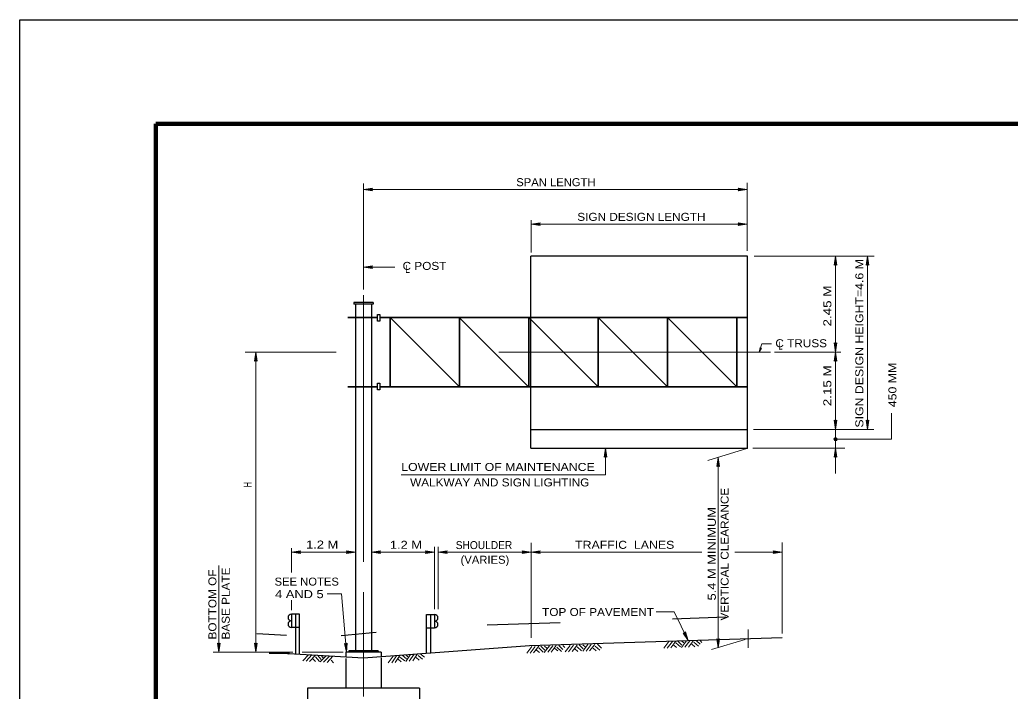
# Model space of a CAD drawing. Extents: x 312601.858 to 312602.699, y 144420.109 to 144420.704.
# Drawn here: x 312601.8578 to 312602.229, y 144420.4517 to 144420.7035 of the extents above; entities that cross this region are included whole.
import ezdxf
from ezdxf.enums import TextEntityAlignment as Align

# ---------------------------------------------------------------- set-up
doc = ezdxf.new("R2010")
doc.units = 0
doc.header["$LTSCALE"] = 0.0012
doc.header["$PDMODE"] = 32
doc.header["$PDSIZE"] = 0.0006
doc.linetypes.add('DOT_DASHED', pattern=[7.7, 5, -1.2, 0.3, -1.2])
doc.linetypes.add('LONG_DASHED', pattern=[7.5, 6, -1.5])
doc.layers.add('1', color=7, linetype='Continuous', lineweight=13)
doc.layers.add('39', color=7, linetype='Continuous', lineweight=13)

msp = doc.modelspace()

# ---------------------------------------------------------------- hatches: boundary and pattern name
at = {"layer": '39'}
for points in [[(312601.9897, 144420.6399), (312601.99, 144420.6394), (312601.9866, 144420.6399), (312601.99, 144420.6404)], [(312602.1274, 144420.6399), (312602.1271, 144420.6404), (312602.1305, 144420.6399), (312602.1271, 144420.6394)], [(312602.0526, 144420.6269), (312602.0529, 144420.6264), (312602.0495, 144420.6269), (312602.0529, 144420.6274)], [(312602.1274, 144420.6269), (312602.1271, 144420.6274), (312602.1305, 144420.6269), (312602.1271, 144420.6264)], [(312602.1636, 144420.6118), (312602.1631, 144420.6115), (312602.1636, 144420.6149), (312602.1641, 144420.6115)], [(312602.1756, 144420.6118), (312602.1751, 144420.6115), (312602.1756, 144420.6149), (312602.1761, 144420.6115)], [(312602.1756, 144420.6118), (312602.1751, 144420.6115), (312602.1756, 144420.6149), (312602.1761, 144420.6115)], [(312602.1756, 144420.6118), (312602.1751, 144420.6115), (312602.1756, 144420.6149), (312602.1761, 144420.6115)], [(312601.9897, 144420.6107), (312601.99, 144420.6102), (312601.9866, 144420.6107), (312601.99, 144420.6112)], [(312601.9897, 144420.6107), (312601.99, 144420.6102), (312601.9866, 144420.6107), (312601.99, 144420.6112)], [(312602.1355, 144420.5804), (312602.1358, 144420.5804), (312602.135, 144420.5789), (312602.1353, 144420.5806)], [(312602.1636, 144420.582), (312602.1641, 144420.5823), (312602.1636, 144420.5789), (312602.1631, 144420.5823)], [(312601.9463, 144420.5758), (312601.9458, 144420.5755), (312601.9463, 144420.5789), (312601.9468, 144420.5755)], [(312601.9463, 144420.5758), (312601.9458, 144420.5755), (312601.9463, 144420.5789), (312601.9468, 144420.5755)], [(312602.1636, 144420.5758), (312602.1631, 144420.5755), (312602.1636, 144420.5789), (312602.1641, 144420.5755)], [(312602.1636, 144420.5758), (312602.1631, 144420.5755), (312602.1636, 144420.5789), (312602.1641, 144420.5755)], [(312602.1636, 144420.553), (312602.1641, 144420.5533), (312602.1636, 144420.5499), (312602.1631, 144420.5533)], [(312602.1636, 144420.553), (312602.1641, 144420.5533), (312602.1636, 144420.5499), (312602.1631, 144420.5533)], [(312602.1636, 144420.553), (312602.1641, 144420.5533), (312602.1636, 144420.5499), (312602.1631, 144420.5533)], [(312602.1756, 144420.553), (312602.1761, 144420.5533), (312602.1756, 144420.5499), (312602.1751, 144420.5533)], [(312602.1756, 144420.553), (312602.1761, 144420.5533), (312602.1756, 144420.5499), (312602.1751, 144420.5533)], [(312602.1756, 144420.553), (312602.1761, 144420.5533), (312602.1756, 144420.5499), (312602.1751, 144420.5533)], [(312602.1642, 144420.5461, 1), (312602.163, 144420.5463, 1)], [(312602.0774, 144420.5398), (312602.0769, 144420.5395), (312602.0774, 144420.5429), (312602.0779, 144420.5395)], [(312602.0774, 144420.5398), (312602.0769, 144420.5395), (312602.0774, 144420.5429), (312602.0779, 144420.5395)], [(312602.1636, 144420.5398), (312602.1631, 144420.5395), (312602.1636, 144420.5429), (312602.1641, 144420.5395)], [(312602.1636, 144420.5398), (312602.1631, 144420.5395), (312602.1636, 144420.5429), (312602.1641, 144420.5395)], [(312602.1636, 144420.5398), (312602.1631, 144420.5395), (312602.1636, 144420.5429), (312602.1641, 144420.5395)], [(312602.1196, 144420.5363), (312602.1191, 144420.536), (312602.1196, 144420.5394), (312602.1201, 144420.536)], [(312601.9627, 144420.5039), (312601.963, 144420.5034), (312601.9596, 144420.5039), (312601.963, 144420.5044)], [(312601.9806, 144420.5039), (312601.9803, 144420.5044), (312601.9837, 144420.5039), (312601.9803, 144420.5034)], [(312601.9927, 144420.5039), (312601.993, 144420.5034), (312601.9896, 144420.5039), (312601.993, 144420.5044)], [(312601.9927, 144420.5039), (312601.993, 144420.5034), (312601.9896, 144420.5039), (312601.993, 144420.5044)], [(312602.0102, 144420.5039), (312602.0099, 144420.5044), (312602.0133, 144420.5039), (312602.0099, 144420.5034)], [(312602.0177, 144420.5039), (312602.018, 144420.5034), (312602.0146, 144420.5039), (312602.018, 144420.5044)], [(312602.0464, 144420.5039), (312602.0461, 144420.5044), (312602.0495, 144420.5039), (312602.0461, 144420.5034)], [(312602.0526, 144420.5039), (312602.0529, 144420.5034), (312602.0495, 144420.5039), (312602.0529, 144420.5044)], [(312602.1405, 144420.5039), (312602.1402, 144420.5044), (312602.1436, 144420.5039), (312602.1402, 144420.5034)], [(312602.107, 144420.4735), (312602.1073, 144420.474), (312602.1083, 144420.4707), (312602.1064, 144420.4735)], [(312601.9324, 144420.4694), (312601.9329, 144420.4697), (312601.9324, 144420.4663), (312601.9319, 144420.4697)], [(312601.9463, 144420.4694), (312601.9468, 144420.4697), (312601.9463, 144420.4663), (312601.9458, 144420.4697)], [(312601.98, 144420.4694), (312601.9805, 144420.4697), (312601.9803, 144420.4663), (312601.9795, 144420.4696)], [(312602.1196, 144420.4711), (312602.1201, 144420.4714), (312602.1196, 144420.468), (312602.1191, 144420.4714)]]:
    msp.add_hatch(color=256, dxfattribs=at).paths.add_polyline_path(points)

# ---------------------------------------------------------------- linework, layer by layer
at = {"layer": '1', "lineweight": 25}
msp.add_line((312601.8578, 144420.7035), (312602.6988, 144420.7035), dxfattribs=at)
at = {"layer": '1'}
for p, q in [((312602.1305, 144420.6168), (312602.1305, 144420.6423)), ((312602.1846, 144420.556), (312602.1846, 144420.5462)), ((312602.1307, 144420.5428), (312602.1157, 144420.5382)), ((312601.9324, 144420.4988), (312601.9324, 144420.4663)), ((312602.0964, 144420.4815), (312602.1031, 144420.4815)), ((312602.1031, 144420.4815), (312602.1083, 144420.4707)), ((312602.0478, 144420.466), (312602.0497, 144420.4685)), ((312602.0491, 144420.466), (312602.051, 144420.4685)), ((312602.0504, 144420.4661), (312602.0523, 144420.4686)), ((312602.0531, 144420.4686), (312602.0546, 144420.4671)), ((312602.0544, 144420.4662), (312602.0563, 144420.4687)), ((312602.0545, 144420.4686), (312602.0553, 144420.4678)), ((312602.0557, 144420.4663), (312602.0576, 144420.4687)), ((312602.057, 144420.4663), (312602.0589, 144420.4688)), ((312602.0591, 144420.4682), (312602.0608, 144420.4666)), ((312602.0599, 144420.4688), (312602.0614, 144420.4674)), ((312602.0613, 144420.4688), (312602.0621, 144420.4681)), ((312602.0622, 144420.4665), (312602.0641, 144420.4689)), ((312602.0635, 144420.4665), (312602.0654, 144420.469)), ((312602.0648, 144420.4666), (312602.0667, 144420.469)), ((312602.0667, 144420.4684), (312602.0684, 144420.4669)), ((312602.0675, 144420.4691), (312602.069, 144420.4676)), ((312602.0688, 144420.4667), (312602.0707, 144420.4692)), ((312602.0689, 144420.4691), (312602.0697, 144420.4683)), ((312602.0701, 144420.4667), (312602.072, 144420.4692)), ((312602.0714, 144420.4668), (312602.0733, 144420.4692)), ((312602.0735, 144420.4686), (312602.0752, 144420.4671)), ((312602.0743, 144420.4693), (312602.0758, 144420.4678)), ((312602.0992, 144420.4679), (312602.1011, 144420.4704)), ((312602.1005, 144420.4679), (312602.1024, 144420.4704)), ((312602.1018, 144420.468), (312602.1037, 144420.4705)), ((312602.1029, 144420.469), (312602.104, 144420.4681)), ((312602.1037, 144420.4699), (312602.1054, 144420.4683)), ((312602.1045, 144420.4705), (312602.106, 144420.469)), ((312602.1058, 144420.4681), (312602.1077, 144420.4706)), ((312602.1059, 144420.4705), (312602.1067, 144420.4698)), ((312602.1071, 144420.4682), (312602.109, 144420.4706)), ((312602.1084, 144420.4682), (312602.1103, 144420.4707)), ((312602.1097, 144420.4693), (312602.1108, 144420.4683)), ((312602.1105, 144420.4701), (312602.1122, 144420.4686)), ((312602.1113, 144420.4707), (312602.1128, 144420.4693)), ((312602.1127, 144420.4708), (312602.1135, 144420.47)), ((312602.1297, 144420.4711), (312602.1171, 144420.4673)), ((312601.9601, 144420.4663), (312601.9303, 144420.4663)), ((312601.979, 144420.4663), (312601.9636, 144420.4663)), ((312601.9639, 144420.4631), (312601.966, 144420.4654)), ((312601.9651, 144420.463), (312601.9673, 144420.4653)), ((312601.9664, 144420.4629), (312601.9686, 144420.4652)), ((312601.9686, 144420.4646), (312601.9701, 144420.4629)), ((312601.9694, 144420.4652), (312601.9708, 144420.4636)), ((312601.9704, 144420.4627), (312601.9726, 144420.465)), ((312601.9708, 144420.4651), (312601.9715, 144420.4642)), ((312601.9717, 144420.4626), (312601.9739, 144420.4649)), ((312601.973, 144420.4625), (312601.9752, 144420.4648)), ((312601.9959, 144420.4623), (312601.9977, 144420.4649)), ((312601.9972, 144420.4624), (312601.999, 144420.465)), ((312601.9985, 144420.4625), (312602.0003, 144420.4651)), ((312602.0003, 144420.4645), (312602.0021, 144420.4631)), ((312602.0011, 144420.4652), (312602.0027, 144420.4638)), ((312602.0025, 144420.4629), (312602.0043, 144420.4655)), ((312602.0025, 144420.4653), (312602.0033, 144420.4646)), ((312602.0038, 144420.463), (312602.0056, 144420.4656)), ((312602.0051, 144420.4631), (312602.0069, 144420.4657)), ((312602.0071, 144420.4651), (312602.0088, 144420.4637)), ((312602.0078, 144420.4658), (312602.0095, 144420.4645)), ((312602.0515, 144420.4671), (312602.0526, 144420.4662)), ((312602.0523, 144420.468), (312602.054, 144420.4664)), ((312602.0584, 144420.4677), (312602.0595, 144420.4668)), ((312602.0659, 144420.4676), (312602.067, 144420.4666)), ((312602.0727, 144420.4678), (312602.0738, 144420.4669)), ((312601.9677, 144420.4639), (312601.9686, 144420.4628)), ((312601.9745, 144420.4634), (312601.9754, 144420.4624)), ((312601.9996, 144420.4637), (312602.0007, 144420.4627)), ((312602.0064, 144420.4643), (312602.0075, 144420.4634))]:
    msp.add_line(p, q, dxfattribs=at)
at = {"layer": '1', "linetype": 'LONG_DASHED', "lineweight": 25}
for p, q in [((312602.1024, 144420.4789), (312602.1224, 144420.4796)), ((312602.033, 144420.4766), (312602.0604, 144420.4775)), ((312601.9466, 144420.4734), (312601.9578, 144420.4727)), ((312601.9783, 144420.4726), (312601.9914, 144420.4738))]:
    msp.add_line(p, q, dxfattribs=at)
at = {"layer": '1', "lineweight": 25}
for points in [[(312601.9919, 144420.5905), (312601.9919, 144420.593), (312601.9927, 144420.593), (312601.9927, 144420.5905)], [(312601.9919, 144420.5647), (312601.9919, 144420.5672), (312601.9927, 144420.5672), (312601.9927, 144420.5647)]]:
    msp.add_lwpolyline(points, close=True, dxfattribs=at)
at = {"layer": '1'}
msp.add_lwpolyline([(312602.1396, 144420.582), (312602.136, 144420.582), (312602.135, 144420.5789)], dxfattribs=at)
at = {"layer": '39', "lineweight": 25}
for p, q in [((312601.8578, 144420.1095), (312601.8578, 144420.7035)), ((312601.983, 144420.5975), (312601.983, 144420.5969)), ((312601.9902, 144420.5975), (312601.983, 144420.5975)), ((312601.9902, 144420.5969), (312601.983, 144420.5969)), ((312601.9836, 144420.5969), (312601.9836, 144420.4669)), ((312601.9896, 144420.5969), (312601.9896, 144420.4669)), ((312601.9902, 144420.5975), (312601.9902, 144420.5969)), ((312601.9611, 144420.4806), (312601.9611, 144420.4657)), ((312601.9626, 144420.4657), (312601.9626, 144420.4806)), ((312602.0103, 144420.4659), (312602.0103, 144420.4805)), ((312602.0118, 144420.4805), (312602.0118, 144420.4661)), ((312601.9626, 144420.4756), (312601.9596, 144420.4756)), ((312601.9626, 144420.4756), (312601.9596, 144420.4756)), ((312602.0103, 144420.4755), (312602.0133, 144420.4755)), ((312602.0103, 144420.4755), (312602.0133, 144420.4755)), ((312601.9586, 144420.4659), (312601.9513, 144420.4659)), ((312601.9932, 144420.4663), (312601.98, 144420.4663)), ((312601.98, 144420.4663), (312601.98, 144420.4646)), ((312601.9921, 144420.4669), (312601.9811, 144420.4669)), ((312601.9811, 144420.4669), (312601.9811, 144420.4663)), ((312601.9921, 144420.4669), (312601.9921, 144420.4663)), ((312601.9932, 144420.4663), (312601.9932, 144420.4647))]:
    msp.add_line(p, q, dxfattribs=at)
at = {"layer": '39', "lineweight": 158}
for p, q in [((312601.9088, 144420.1247), (312601.9088, 144420.6645)), ((312601.9088, 144420.6645), (312602.6838, 144420.6645))]:
    msp.add_line(p, q, dxfattribs=at)
at = {"layer": '39'}
for p, q in [((312601.9866, 144420.6421), (312601.9866, 144420.6024)), ((312602.1305, 144420.6399), (312601.9866, 144420.6399)), ((312602.0495, 144420.6162), (312602.0495, 144420.6283)), ((312602.1305, 144420.6269), (312602.0495, 144420.6269)), ((312602.1781, 144420.6149), (312602.1331, 144420.6149)), ((312602.1756, 144420.5499), (312602.1756, 144420.6149)), ((312601.9866, 144420.6107), (312601.9984, 144420.6107)), ((312601.9764, 144420.5789), (312601.9423, 144420.5789)), ((312601.9463, 144420.4663), (312601.9463, 144420.5789)), ((312602.1407, 144420.5789), (312602.1655, 144420.5789)), ((312602.1328, 144420.5499), (312602.1779, 144420.5499)), ((312602.1846, 144420.5462), (312602.1638, 144420.5462)), ((312602.0774, 144420.5329), (312602.0774, 144420.5429)), ((312602.1326, 144420.5429), (312602.167, 144420.5429)), ((312602.1196, 144420.5394), (312602.1196, 144420.468)), ((312602.0007, 144420.5329), (312602.0774, 144420.5329)), ((312601.9596, 144420.5054), (312601.9596, 144420.4962)), ((312602.0133, 144420.5059), (312602.0133, 144420.4825)), ((312602.0146, 144420.5059), (312602.0146, 144420.4825)), ((312602.0495, 144420.5073), (312602.0495, 144420.4717)), ((312602.1436, 144420.5075), (312602.1436, 144420.4734)), ((312601.9836, 144420.5039), (312601.9596, 144420.5039)), ((312602.0133, 144420.5039), (312601.9896, 144420.5039)), ((312602.0495, 144420.5039), (312602.0146, 144420.5039)), ((312602.1135, 144420.5039), (312602.0495, 144420.5039)), ((312602.1436, 144420.5039), (312602.1258, 144420.5039)), ((312601.9784, 144420.4882), (312601.973, 144420.4882)), ((312601.9784, 144420.4882), (312601.9803, 144420.4663)), ((312601.9596, 144420.4859), (312601.9596, 144420.4821)), ((312601.9611, 144420.4806), (312601.9611, 144420.4676)), ((312602.0118, 144420.4805), (312602.0118, 144420.4675)), ((312601.9626, 144420.4791), (312601.9626, 144420.4657)), ((312602.1308, 144420.468), (312602.1308, 144420.4748))]:
    msp.add_line(p, q, dxfattribs=at)
at = {"layer": '39', "linetype": 'LONG_DASHED', "lineweight": 25}
for p, q in [((312602.1306, 144420.6149), (312602.0494, 144420.6149)), ((312602.0494, 144420.5429), (312602.0494, 144420.6149)), ((312602.1306, 144420.5429), (312602.1306, 144420.6149)), ((312602.0495, 144420.5499), (312602.1306, 144420.5499)), ((312602.0494, 144420.5429), (312602.1306, 144420.5429)), ((312601.98, 144420.464), (312601.98, 144420.4529)), ((312601.9932, 144420.4642), (312601.9932, 144420.4529)), ((312602.0076, 144420.4529), (312601.9656, 144420.4529)), ((312601.9656, 144420.4529), (312601.9656, 144420.4449)), ((312602.0076, 144420.4529), (312602.0076, 144420.4449))]:
    msp.add_line(p, q, dxfattribs=at)
at = {"layer": '39', "linetype": 'DOT_DASHED'}
for p, q in [((312601.9866, 144420.6002), (312601.9866, 144420.4881)), ((312602.1374, 144420.5789), (312601.9776, 144420.5789)), ((312602.1351, 144420.5789), (312602.1392, 144420.5789)), ((312601.9866, 144420.4888), (312601.9866, 144420.4497))]:
    msp.add_line(p, q, dxfattribs=at)
at = {"layer": '39', "lineweight": 35}
for p, q in [((312601.9919, 144420.5919), (312601.9807, 144420.5919)), ((312602.1305, 144420.5919), (312601.9927, 144420.5919)), ((312601.9966, 144420.5919), (312601.9966, 144420.5659)), ((312602.0226, 144420.5659), (312601.9966, 144420.5919)), ((312602.0485, 144420.5659), (312602.0225, 144420.5919)), ((312602.0226, 144420.5919), (312602.0226, 144420.5659)), ((312602.0486, 144420.5919), (312602.0486, 144420.5659)), ((312602.0746, 144420.5659), (312602.0486, 144420.5919)), ((312602.0746, 144420.5919), (312602.0746, 144420.5659)), ((312602.1006, 144420.5659), (312602.0746, 144420.5919)), ((312602.1006, 144420.5919), (312602.1006, 144420.5659)), ((312602.1266, 144420.5659), (312602.1006, 144420.5919)), ((312602.1266, 144420.5659), (312602.1266, 144420.5919)), ((312601.9807, 144420.5659), (312601.9919, 144420.5659)), ((312601.9927, 144420.5659), (312602.1307, 144420.5659))]:
    msp.add_line(p, q, dxfattribs=at)
at = {"layer": '39'}
for points in [[(312601.9897, 144420.6399), (312601.99, 144420.6394), (312601.9866, 144420.6399), (312601.99, 144420.6404)], [(312602.1274, 144420.6399), (312602.1271, 144420.6404), (312602.1305, 144420.6399), (312602.1271, 144420.6394)], [(312602.0526, 144420.6269), (312602.0529, 144420.6264), (312602.0495, 144420.6269), (312602.0529, 144420.6274)], [(312602.1274, 144420.6269), (312602.1271, 144420.6274), (312602.1305, 144420.6269), (312602.1271, 144420.6264)], [(312602.1636, 144420.6118), (312602.1631, 144420.6115), (312602.1636, 144420.6149), (312602.1641, 144420.6115)], [(312602.1756, 144420.6118), (312602.1751, 144420.6115), (312602.1756, 144420.6149), (312602.1761, 144420.6115)], [(312602.1756, 144420.6118), (312602.1751, 144420.6115), (312602.1756, 144420.6149), (312602.1761, 144420.6115)], [(312602.1756, 144420.6118), (312602.1751, 144420.6115), (312602.1756, 144420.6149), (312602.1761, 144420.6115)], [(312601.9897, 144420.6107), (312601.99, 144420.6102), (312601.9866, 144420.6107), (312601.99, 144420.6112)], [(312601.9897, 144420.6107), (312601.99, 144420.6102), (312601.9866, 144420.6107), (312601.99, 144420.6112)], [(312602.1355, 144420.5804), (312602.1358, 144420.5804), (312602.135, 144420.5789), (312602.1353, 144420.5806)], [(312602.1636, 144420.582), (312602.1641, 144420.5823), (312602.1636, 144420.5789), (312602.1631, 144420.5823)], [(312601.9463, 144420.5758), (312601.9458, 144420.5755), (312601.9463, 144420.5789), (312601.9468, 144420.5755)], [(312601.9463, 144420.5758), (312601.9458, 144420.5755), (312601.9463, 144420.5789), (312601.9468, 144420.5755)], [(312602.1636, 144420.5758), (312602.1631, 144420.5755), (312602.1636, 144420.5789), (312602.1641, 144420.5755)], [(312602.1636, 144420.5758), (312602.1631, 144420.5755), (312602.1636, 144420.5789), (312602.1641, 144420.5755)], [(312602.1636, 144420.553), (312602.1641, 144420.5533), (312602.1636, 144420.5499), (312602.1631, 144420.5533)], [(312602.1636, 144420.553), (312602.1641, 144420.5533), (312602.1636, 144420.5499), (312602.1631, 144420.5533)], [(312602.1636, 144420.553), (312602.1641, 144420.5533), (312602.1636, 144420.5499), (312602.1631, 144420.5533)], [(312602.1756, 144420.553), (312602.1761, 144420.5533), (312602.1756, 144420.5499), (312602.1751, 144420.5533)], [(312602.1756, 144420.553), (312602.1761, 144420.5533), (312602.1756, 144420.5499), (312602.1751, 144420.5533)], [(312602.1756, 144420.553), (312602.1761, 144420.5533), (312602.1756, 144420.5499), (312602.1751, 144420.5533)], [(312602.0774, 144420.5398), (312602.0769, 144420.5395), (312602.0774, 144420.5429), (312602.0779, 144420.5395)], [(312602.0774, 144420.5398), (312602.0769, 144420.5395), (312602.0774, 144420.5429), (312602.0779, 144420.5395)], [(312602.1636, 144420.5398), (312602.1631, 144420.5395), (312602.1636, 144420.5429), (312602.1641, 144420.5395)], [(312602.1636, 144420.5398), (312602.1631, 144420.5395), (312602.1636, 144420.5429), (312602.1641, 144420.5395)], [(312602.1636, 144420.5398), (312602.1631, 144420.5395), (312602.1636, 144420.5429), (312602.1641, 144420.5395)], [(312602.1196, 144420.5363), (312602.1191, 144420.536), (312602.1196, 144420.5394), (312602.1201, 144420.536)], [(312601.9627, 144420.5039), (312601.963, 144420.5034), (312601.9596, 144420.5039), (312601.963, 144420.5044)], [(312601.9806, 144420.5039), (312601.9803, 144420.5044), (312601.9837, 144420.5039), (312601.9803, 144420.5034)], [(312601.9927, 144420.5039), (312601.993, 144420.5034), (312601.9896, 144420.5039), (312601.993, 144420.5044)], [(312601.9927, 144420.5039), (312601.993, 144420.5034), (312601.9896, 144420.5039), (312601.993, 144420.5044)], [(312602.0102, 144420.5039), (312602.0099, 144420.5044), (312602.0133, 144420.5039), (312602.0099, 144420.5034)], [(312602.0177, 144420.5039), (312602.018, 144420.5034), (312602.0146, 144420.5039), (312602.018, 144420.5044)], [(312602.0464, 144420.5039), (312602.0461, 144420.5044), (312602.0495, 144420.5039), (312602.0461, 144420.5034)], [(312602.0526, 144420.5039), (312602.0529, 144420.5034), (312602.0495, 144420.5039), (312602.0529, 144420.5044)], [(312602.1405, 144420.5039), (312602.1402, 144420.5044), (312602.1436, 144420.5039), (312602.1402, 144420.5034)], [(312602.107, 144420.4735), (312602.1073, 144420.474), (312602.1083, 144420.4707), (312602.1064, 144420.4735)], [(312601.9324, 144420.4694), (312601.9329, 144420.4697), (312601.9324, 144420.4663), (312601.9319, 144420.4697)], [(312601.9463, 144420.4694), (312601.9468, 144420.4697), (312601.9463, 144420.4663), (312601.9458, 144420.4697)], [(312601.98, 144420.4694), (312601.9805, 144420.4697), (312601.9803, 144420.4663), (312601.9795, 144420.4696)], [(312602.1196, 144420.4711), (312602.1201, 144420.4714), (312602.1196, 144420.468), (312602.1191, 144420.4714)]]:
    msp.add_lwpolyline(points, close=True, dxfattribs=at)
for points in [[(312602.1636, 144420.5334), (312602.1636, 144420.5429), (312602.1636, 144420.5499), (312602.1636, 144420.5789), (312602.1636, 144420.6149)], [(312601.9626, 144420.4806), (312601.9596, 144420.4806), (312601.9596, 144420.4756)], [(312602.0103, 144420.4805), (312602.0133, 144420.4805), (312602.0133, 144420.4755)]]:
    msp.add_lwpolyline(points, dxfattribs=at)
at = {"layer": '39', "lineweight": 25}
for points in [[(312601.9626, 144420.4806), (312601.9596, 144420.4806), (312601.9596, 144420.4756)], [(312602.0103, 144420.4805), (312602.0133, 144420.4805), (312602.0133, 144420.4755)], [(312601.9586, 144420.4659), (312601.9866, 144420.4642), (312602.0489, 144420.4688), (312602.1436, 144420.4719)]]:
    msp.add_lwpolyline(points, dxfattribs=at)
at = {"layer": '39'}
msp.add_circle((312602.1636, 144420.5462), 0.000608, dxfattribs=at)
at = {"layer": '39', "lineweight": 25}
for centre, start, end in [((312601.9596, 144420.47935), 90, 270), ((312602.0133, 144420.47925), 270, 90), ((312601.9596, 144420.47685), 90, 270), ((312602.0133, 144420.47675), 270, 90)]:
    msp.add_arc(centre, 0.00125, start, end, dxfattribs=at)
at = {"layer": '39'}
for centre, start, end in [((312601.9596, 144420.47935), 90, 270), ((312602.0133, 144420.47925), 270, 90), ((312601.9596, 144420.47685), 90, 270), ((312602.0133, 144420.47675), 270, 90)]:
    msp.add_arc(centre, 0.00125, start, end, dxfattribs=at)
msp.add_point((312601.9585, 144420.4659), dxfattribs=at)

# ---------------------------------------------------------------- texts
at = {"layer": '1'}
for s, width, p in [('SPAN LENGTH', 1.05, (312602.05875, 144420.6411)), ('SIGN DESIGN LENGTH', 1.1, (312602.0908, 144420.6281)), ('C POST', 1.1, (312602.0095, 144420.6097)), ('L', 0.75, (312602.00315, 144420.6086)), ('C TRUSS', 1.1, (312602.1507, 144420.5807)), ('L', 0.75, (312602.14295, 144420.5798)), ('1.2 M', 1.2, (312601.97115, 144420.5052)), ('1.2 M', 1.2, (312602.00255, 144420.5051)), ('SHOULDER', 0.95, (312602.0318, 144420.505)), ('(VARIES)', 1.05, (312602.03215, 144420.4995)), ('TOP OF PAVEMENT', 1.1, (312602.07455, 144420.4799))]:
    msp.add_text(s, height=0.003, dxfattribs=dict(at, width=width)).set_placement(p, align=Align.CENTER)
for s, width, p in [('2.45 M', 1.25, (312602.162, 144420.59615)), ('2.15 M ', 1.25, (312602.162, 144420.56695)), ('450 MM', 1.15, (312602.1864, 144420.56655)), ('H', 0.6, (312601.9447, 144420.52915)), ('VERTICAL CLEARANCE', 1.1, (312602.1235, 144420.5031)), ('5.4 M MINIMUM', 1.2, (312602.1187, 144420.50325))]:
    msp.add_text(s, height=0.003, rotation=90, dxfattribs=dict(at, width=width)).set_placement(p, align=Align.CENTER)
at = {"layer": '1', "width": 1.1}
for s, p in [('BASE PLATE', (312601.9365, 144420.4711)), ('BOTTOM OF', (312601.9315, 144420.4711))]:
    msp.add_text(s, height=0.003, rotation=90, dxfattribs=at).set_placement(p)
at = {"layer": '1'}
for s, width, p in [('SEE NOTES', 1.05, (312601.9533, 144420.4913)), ('4 AND 5', 1.2, (312601.9535, 144420.4866))]:
    msp.add_text(s, height=0.003, dxfattribs=dict(at, width=width)).set_placement(p)
at = {"layer": '39', "width": 1.15}
msp.add_text('SIGN DESIGN HEIGHT=4.6 M', height=0.003, rotation=90, dxfattribs=at).set_placement((312602.174, 144420.58215), align=Align.CENTER)
at = {"layer": '39'}
for s, width, p in [('LOWER LIMIT OF MAINTENANCE', 1.15, (312602.03705, 144420.5343)), ('WALKWAY AND SIGN LIGHTING', 1.1, (312602.0377, 144420.5285)), ('TRAFFIC  LANES', 1.15, (312602.08455, 144420.5051))]:
    msp.add_text(s, height=0.003, dxfattribs=dict(at, width=width)).set_placement(p, align=Align.CENTER)

doc.saveas('drawing.dxf')
